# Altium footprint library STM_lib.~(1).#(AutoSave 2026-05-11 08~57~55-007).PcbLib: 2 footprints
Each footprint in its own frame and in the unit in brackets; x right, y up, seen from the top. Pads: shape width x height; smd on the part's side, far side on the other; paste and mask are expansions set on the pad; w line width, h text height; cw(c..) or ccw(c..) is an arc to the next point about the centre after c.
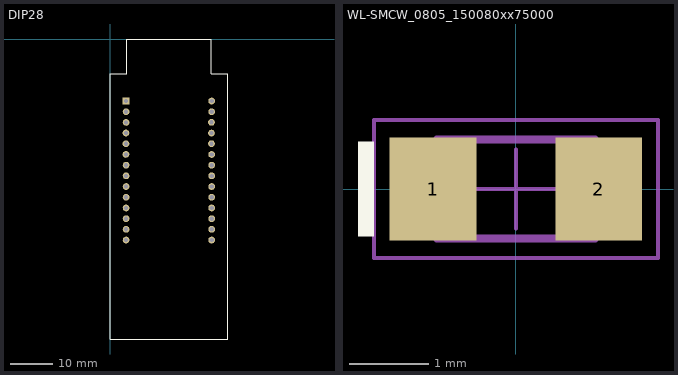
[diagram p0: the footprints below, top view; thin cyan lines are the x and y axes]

## DIP28 [mm]
pads (28):
  rect 1.6x1.6 hole 1: 1(3.81,-14.732)
  round 1.6 hole 1: 2(3.81,-17.272) 3(3.81,-19.812) 4(3.772,-22.328) 5(3.772,-24.889) 6(3.772,-27.408) 7(3.81,-29.972) 8(3.81,-32.512) 9(3.81,-35.052) 10(3.81,-37.592) 11(3.81,-40.132) 12(3.81,-42.672) 13(3.81,-45.212) 14(3.81,-47.752) 15(24.13,-14.732) 16(24.13,-17.272) 17(24.092,-19.788) 18(24.092,-22.349) 19(24.092,-24.868) 20(24.13,-27.432) 21(24.13,-29.972) 22(24.13,-32.512) 23(24.13,-35.052) 24(24.13,-37.592) 25(24.13,-40.132) 26(24.13,-42.672) 27(24.13,-45.212) 28(24.13,-47.752)
Top Overlay:
  lines w0.254: 0,-71.26 28,-71.26 28,-8.26 24.068,-8.26 24.068,0 3.932,0 3.932,-8.26 0,-8.26 0,-71.26

## WL-SMCW_0805_150080xx75000 [mm] "SMD Mono-color Chip LED, body 2.0x1.25mm"
height 0.7
pads (2):
  rect 1.1x1.3 smd: 1(-1.05,0) 2(1.05,0)
Top Overlay:
  rectangle: -2,-0.6 -1.8,0.6
Top Component Outline:
  rectangle: -1,-0.625 -0.7,0.625
  lines w0.1: -1,-0.625 1,-0.625 1,0.625 -1,0.625 -1,-0.625
Top Courtyard:
  lines w0.05: -1.8,-0.875 1.8,-0.875 1.8,0.875 -1.8,0.875 -1.8,-0.875
Top Component Center:
  lines w0.05: -0.5,0 0.5,0 ; 0,-0.5 0,0.5
Top Designator:
  text ".Designator" at -2.499,-0.167 h0.5
3D body "150080xxS75000.stp": height 0.7, standoff 0, extent -1,-0.625 1,0.625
